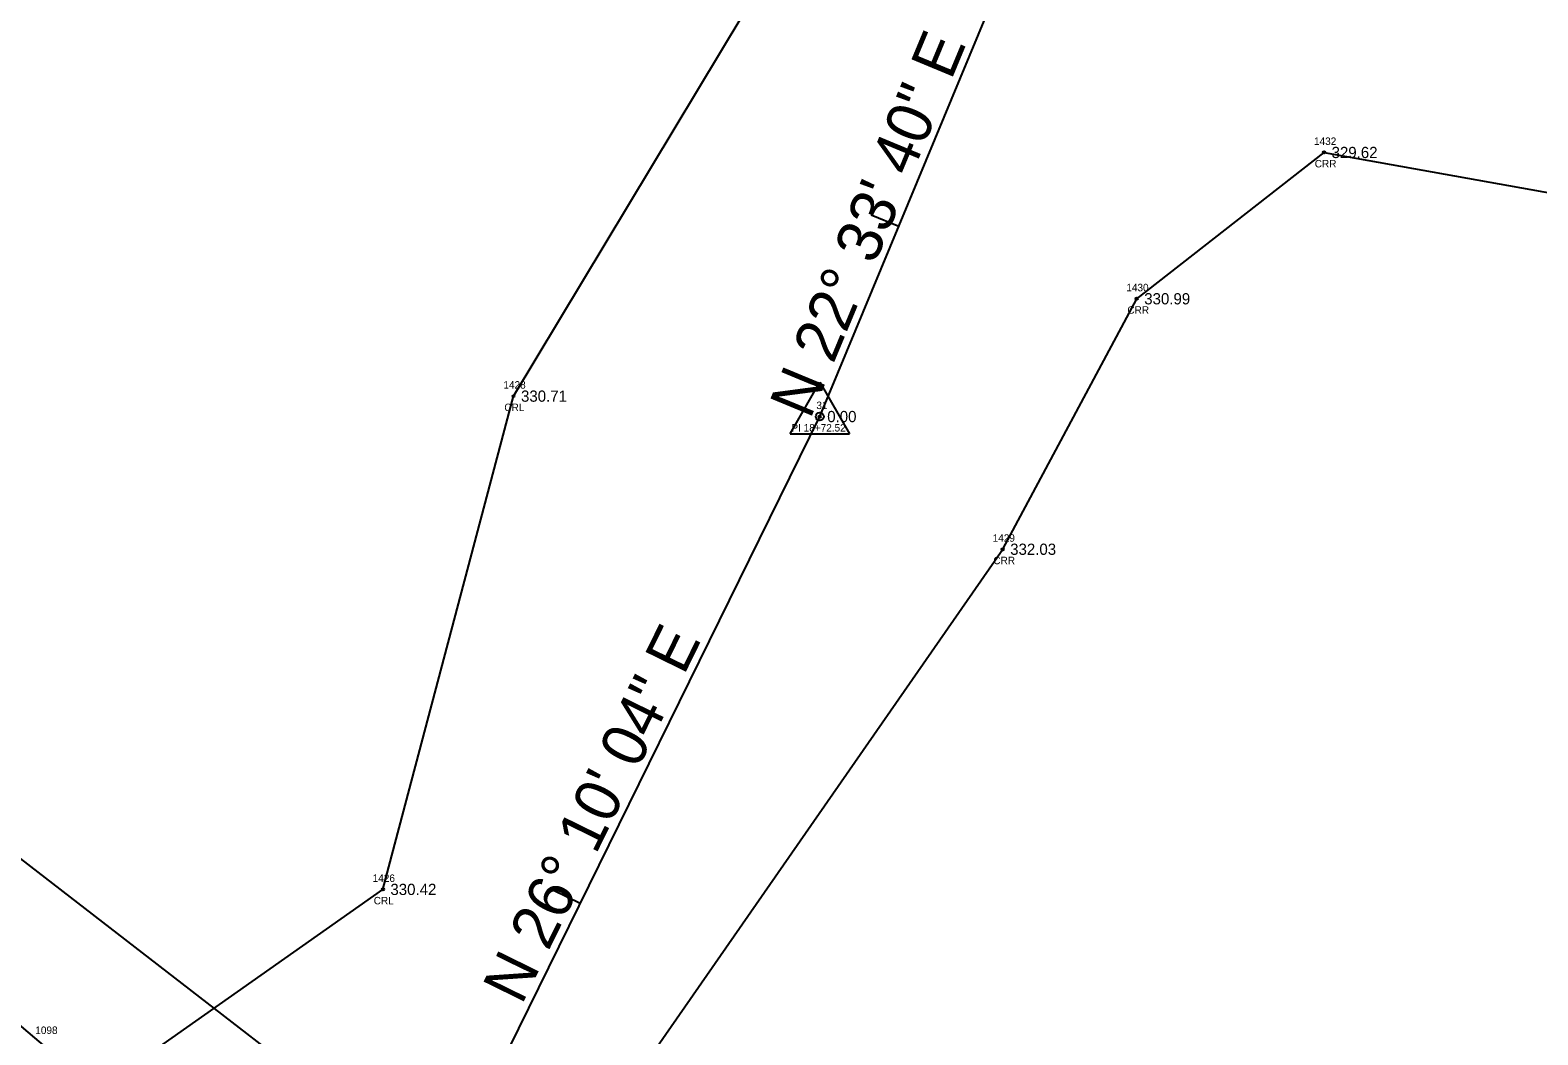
# Model space of a CAD drawing. Extents: x 2006517 to 2008868, y 1001613 to 1004633.
# Drawn here: x 2007831.6 to 2008032.9, y 1002981.4 to 1003115.7 of the extents above; entities that cross this region are included whole.
import ezdxf

# ---------------------------------------------------------------- set-up
doc = ezdxf.new("R2010")
doc.units = 0
for name, color, linetype in [('RD_EX_Bridge_txCode', 7, 'Continuous'), ('RD_EX_GuardRail', 7, 'Continuous'), ('RD_EX_H2O', 7, 'Continuous'), ('RD_EX_H2O_txCode', 7, 'Continuous'), ('RD_EX_TX_H2O_ELEV', 7, 'Continuous'), ('RD_EX_VEG', 7, 'Continuous'), ('RD_HC_Cl', 7, 'Continuous'), ('RD_HC_Data', 7, 'Continuous'), ('RD_HC_Data_Tic', 7, 'Continuous'), ('RD_HC_Survey_ELEV', 7, 'Continuous'), ('RD_HC_txCode', 7, 'Continuous'), ('RD_SMD_Locator', 7, 'Continuous')]:
    doc.layers.add(name, color=color, linetype=linetype)

msp = doc.modelspace()

# ---------------------------------------------------------------- linework, layer by layer
at = {"layer": 'RD_EX_GuardRail'}
msp.add_lwpolyline([(2007643.64, 1003141.95), (2007706.71, 1003087.87), (2007781.32, 1003024.2), (2007854.58, 1002961.97), (2007936.8, 1002891.67), (2008015.14, 1002821.85)], dxfattribs=at)
at = {"layer": 'RD_EX_H2O'}
for points in [[(2007566.26, 1003088.08), (2007592.77, 1003066.93), (2007644.53, 1003029.41), (2007702.53, 1002994.39), (2007770.87, 1002943.23), (2007791.99, 1002931.5), (2007811.28, 1002935.75), (2007819.82, 1002947.27), (2007841.83, 1002974.87), (2007878.69, 1003000.86), (2007896.13, 1003066.77), (2007932.98, 1003128.11), (2007999.19, 1003157.72), (2008050.1, 1003143.6), (2008100.83, 1003134.29), (2008155.79, 1003098.62), (2008198.7, 1003074.43), (2008262, 1003078.26), (2008305.31, 1003092.03)], [(2007669.06, 1002953.29), (2007739.37, 1002899.33), (2007777.17, 1002873.15), (2007843, 1002887.34), (2007865.59, 1002908.46), (2007889.4, 1002933.96), (2007902.62, 1002951.59), (2007899.23, 1002956.7), (2007961.45, 1003046.31), (2007979.35, 1003079.78), (2008004.37, 1003099.33), (2008040.91, 1003092.79), (2008074.17, 1003079.43), (2008125.54, 1003053.8), (2008176.9, 1003027.12), (2008276.14, 1003020.76), (2008327.51, 1003029.06)]]:
    msp.add_lwpolyline(points, dxfattribs=at)
at = {"layer": 'RD_EX_VEG'}
msp.add_lwpolyline([(2007473.93, 1003322.69), (2007503.07, 1003282.99), (2007540.25, 1003252.05), (2007579.27, 1003219.13), (2007642.18, 1003150.48), (2007952.5, 1002910.4), (2008017.59, 1002836.73), (2008047.98, 1002799.05), (2008087.42, 1002767.09), (2008121.48, 1002729.06), (2008151.49, 1002690.42), (2008185.86, 1002650.76), (2008208.76, 1002609.15), (2008254.04, 1002533.01), (2008311.38, 1002450.28), (2008360.35, 1002372.97), (2008409.06, 1002292.02), (2008460.63, 1002215.28), (2008512.48, 1002133.62), (2008564.88, 1002053.16), (2008614.62, 1001980.71), (2008661.43, 1001938.2)], dxfattribs=at)
at = {"layer": 'RD_HC_Cl'}
for p, q in [((2007937.02, 1003064.04), (2007959.44, 1003118)), ((2007883.99, 1002956.11), (2007937.02, 1003064.04))]:
    msp.add_line(p, q, dxfattribs=at)
at = {"layer": 'RD_HC_Data'}
for p, q in [((2007933.05, 1003061.75), (2007937.02, 1003068.63)), ((2007937.02, 1003068.63), (2007940.99, 1003061.75)), ((2007933.05, 1003061.75), (2007940.99, 1003061.75))]:
    msp.add_line(p, q, dxfattribs=at)
msp.add_circle((2007937.02, 1003064.04), 0.529, dxfattribs=at)
at = {"layer": 'RD_HC_Data_Tic'}
for p, q in [((2007947.56, 1003089.42), (2007943.87, 1003090.95)), ((2007905.04, 1002998.96), (2007901.45, 1003000.72))]:
    msp.add_line(p, q, dxfattribs=at)
at = {"layer": 'RD_SMD_Locator'}
for centre in [(2008004.37, 1003099.33), (2007979.35, 1003079.78), (2007896.13, 1003066.77), (2007937.02, 1003064.04), (2007961.45, 1003046.31), (2007878.69, 1003000.86)]:
    msp.add_circle(centre, 0.15, dxfattribs=at)

# ---------------------------------------------------------------- texts
at = {"layer": 'RD_EX_Bridge_txCode'}
msp.add_text('1098', height=1, dxfattribs=at).set_placement((2007832.27, 1002981.54))
at = {"layer": 'RD_EX_H2O_txCode'}
for s, p in [('1432', (2008003.02, 1003100.33)), ('CRR', (2008003.12, 1003097.33)), ('1430', (2007977.96, 1003080.78)), ('CRR', (2007978.1, 1003077.78)), ('1428', (2007894.78, 1003067.77)), ('CRL', (2007894.9, 1003064.77)), ('1429', (2007960.11, 1003047.31)), ('CRR', (2007960.2, 1003044.31)), ('1426', (2007877.32, 1003001.86)), ('CRL', (2007877.46, 1002998.86))]:
    msp.add_text(s, height=1, dxfattribs=at).set_placement(p)
at = {"layer": 'RD_EX_TX_H2O_ELEV'}
for s, p in [('329.62', (2008005.37, 1003098.58)), ('330.99', (2007980.35, 1003079.03)), ('330.71', (2007897.13, 1003066.02)), ('332.03', (2007962.45, 1003045.56)), ('330.42', (2007879.69, 1003000.11))]:
    msp.add_text(s, height=1.5, dxfattribs=at).set_placement(p)
at = {"layer": 'RD_HC_Data'}
for s, rotation, p in [('N 22%%d 33\' 40" E', 67.4389, (2007935.73, 1003063.55)), ('N 26%%d 10\' 04" E', 63.8321, (2007897.22, 1002985.31))]:
    msp.add_text(s, height=6, rotation=rotation, dxfattribs=at).set_placement(p)
at = {"layer": 'RD_HC_Survey_ELEV'}
msp.add_text('0.00', height=1.5, dxfattribs=at).set_placement((2007938.02, 1003063.29))
at = {"layer": 'RD_HC_txCode'}
for s, p in [('31', (2007936.57, 1003065.04)), ('PI 18+72.52', (2007933.24, 1003062.04))]:
    msp.add_text(s, height=1, dxfattribs=at).set_placement(p)

doc.saveas('drawing.dxf')
